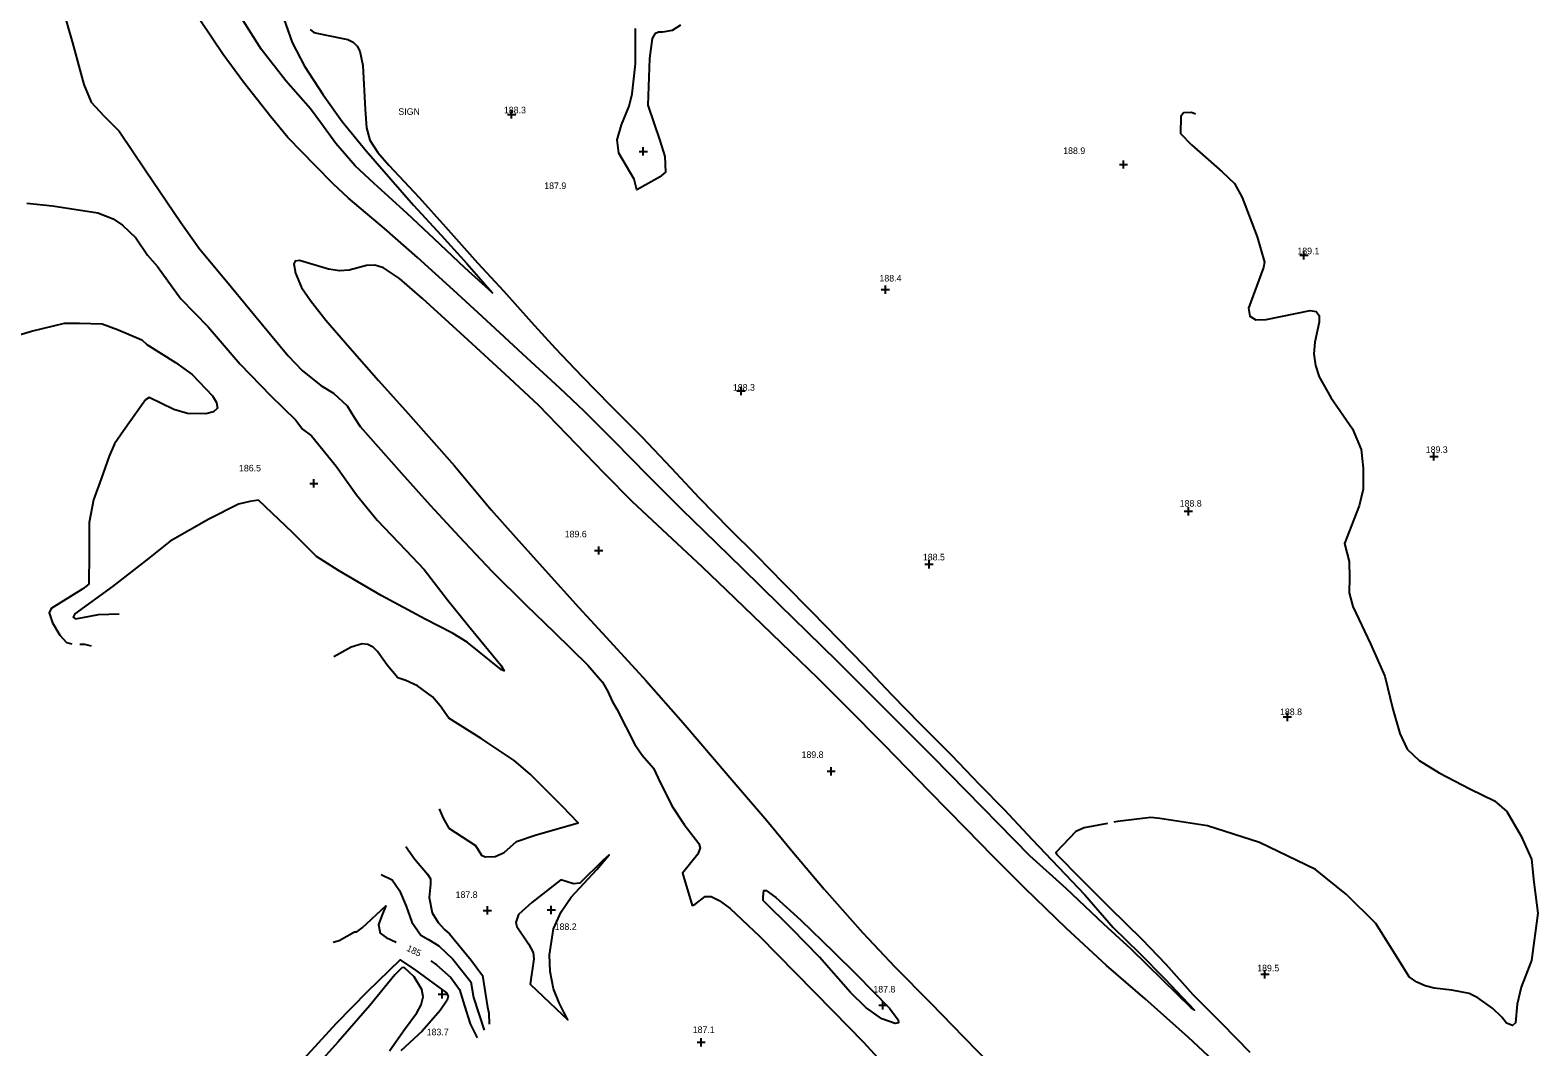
# Model space of a CAD drawing. Extents: x 1467615 to 2003689, y 770235 to 1108726.
# Drawn here: x 1992388.4 to 1992847, y 779287.2 to 779596.3 of the extents above; entities that cross this region are included whole.
import ezdxf

# ---------------------------------------------------------------- set-up
doc = ezdxf.new("R2010")
doc.units = 0
for name, color, linetype in [('RD_DTM_Major1', 7, 'Continuous'), ('RD_DTM_Major1_Lbl', 7, 'Continuous'), ('RD_DTM_Minor1', 7, 'Continuous'), ('RD_DTM_Spot_Elev', 7, 'Continuous'), ('RD_TX_Misc1', 7, 'Continuous')]:
    doc.layers.add(name, color=color, linetype=linetype)

msp = doc.modelspace()

# ---------------------------------------------------------------- linework, layer by layer
at = {"layer": 'RD_DTM_Major1'}
for points in [[(1992480.58, 779319.07), (1992482.42, 779319.56), (1992487.05, 779322.18), (1992487.72, 779322.15), (1992489.4, 779323.42), (1992496.59, 779330.15), (1992495.51, 779327.35), (1992494.38, 779324.42), (1992494.84, 779321.83), (1992496.64, 779320.52), (1992499.68, 779319.07)], [(1992510.25, 779313.36), (1992512.04, 779312.16), (1992516.33, 779308.33), (1992519.04, 779304.69), (1992520.5, 779299.72), (1992522.26, 779294.27), (1992524.38, 779289.97)]]:
    msp.add_lwpolyline(points, dxfattribs=at)
at = {"layer": 'RD_DTM_Minor1'}
for points in [[(1992397.98, 779603.75), (1992401.25, 779592.5), (1992404.72, 779579.82), (1992406.98, 779574.5), (1992410.81, 779570.32), (1992415.5, 779565.64), (1992423.59, 779553.57), (1992434.18, 779537.86), (1992439.93, 779529.87), (1992448.13, 779520), (1992456.66, 779509.71), (1992466.91, 779497.35), (1992471.17, 779492.87), (1992476.81, 779488.33), (1992480.7, 779486.02), (1992484.78, 779482.09), (1992487.02, 779478.47), (1992488.77, 779475.85), (1992494.27, 779469.65), (1992501.33, 779461.64), (1992510.06, 779451.97), (1992518.91, 779442.4), (1992528.86, 779431.83), (1992539.12, 779421.62), (1992547.74, 779413.31), (1992558.03, 779403.23), (1992562.51, 779398.07), (1992564.06, 779395.27), (1992565.43, 779392.38), (1992566.86, 779389.91), (1992572.37, 779379.15), (1992574.55, 779375.91), (1992577.97, 779371.95), (1992579.44, 779368.88), (1992583.55, 779360.49), (1992587.35, 779354.79), (1992591.82, 779349.03), (1992592.18, 779347.75), (1992591.46, 779345.84), (1992586.83, 779340.08), (1992589.79, 779330.2), (1992590.55, 779330.55), (1992593.75, 779332.99), (1992595.5, 779332.91), (1992597.99, 779331.77), (1992601.33, 779329.26), (1992610.23, 779320.84), (1992621.22, 779309.71), (1992632.57, 779298.2), (1992641.91, 779288.67), (1992649.62, 779280.19)], [(1992464.22, 779603.56), (1992468.11, 779592.6), (1992471.87, 779585.45), (1992477.47, 779576.7), (1992483.28, 779568.57), (1992490.58, 779559.69), (1992498.09, 779551.05), (1992505.04, 779543.12), (1992513.41, 779534.03), (1992521.22, 779525.44), (1992529.02, 779516.44), (1992520.62, 779524.12), (1992511.32, 779532.87), (1992503.09, 779540.6), (1992493.08, 779549.71), (1992487.3, 779555.11), (1992481.33, 779561.92), (1992476.78, 779568.13), (1992473.65, 779572.42), (1992466.21, 779580.9), (1992458.65, 779590.6), (1992452.61, 779600.22)], [(1992473.56, 779596.5), (1992474.72, 779595.64), (1992477.99, 779594.89), (1992484.98, 779593.51), (1992486.67, 779592.67), (1992487.89, 779591.51), (1992488.72, 779589.98), (1992489.57, 779585.59), (1992490.31, 779572.27), (1992490.68, 779566.61), (1992491.76, 779562.9), (1992494.14, 779559.17), (1992497.53, 779555.34), (1992506.7, 779545.51), (1992514.77, 779536.57), (1992524.46, 779525.65), (1992532.48, 779516.95), (1992540.8, 779507.71), (1992548.1, 779499.62), (1992556.16, 779491.1), (1992565.07, 779482.11), (1992574.46, 779472.72), (1992583.38, 779463.25), (1992591.91, 779454.17), (1992601.12, 779444.7), (1992609.22, 779436.71), (1992617.59, 779428.19), (1992625.96, 779419.69), (1992634.4, 779411.13), (1992642.06, 779403.18), (1992650.36, 779394.35), (1992659.17, 779385.34), (1992668.62, 779375.91), (1992677.16, 779367.01), (1992684.66, 779359.35), (1992693.19, 779350.27), (1992701.2, 779341.82), (1992709.19, 779333.47), (1992717.87, 779323.49), (1992725.69, 779315.77), (1992733.53, 779307.88), (1992742.6, 779298.34), (1992741.56, 779299.11), (1992732.98, 779307.5), (1992723.25, 779316.9), (1992714.97, 779324.54), (1992703.51, 779335.38), (1992692.46, 779345.32), (1992683.03, 779354.91), (1992673.15, 779365.03), (1992662.88, 779375.53), (1992656.21, 779382.23), (1992645.02, 779393.37), (1992633.94, 779404.37), (1992624.74, 779413.41), (1992616.44, 779421.55), (1992605.12, 779432.64), (1992593.37, 779444.06), (1992586.74, 779450.55), (1992576.41, 779460.88), (1992566.11, 779471.27), (1992556.96, 779480.46), (1992549.53, 779487.47), (1992539.6, 779496.66), (1992527.19, 779508.06), (1992517.17, 779517.29), (1992506.25, 779527.27), (1992496.18, 779536), (1992485.23, 779545.22), (1992480.58, 779549.62), (1992475.23, 779555.12), (1992466.78, 779563.68), (1992461.65, 779570), (1992453.27, 779580.58), (1992447.06, 779588.96), (1992440.24, 779599.19)], [(1992586.26, 779597.87), (1992583.64, 779596.24), (1992580.78, 779595.77), (1992579.5, 779595.71), (1992578.41, 779595.2), (1992577.58, 779593.77), (1992576.75, 779587.76), (1992576.29, 779573.53), (1992579.9, 779562.82), (1992581.42, 779557.94), (1992581.61, 779553.14), (1992579.8, 779551.66), (1992572.9, 779547.83), (1992572.12, 779551), (1992567.42, 779558.91), (1992566.98, 779563), (1992568.25, 779567.57), (1992570.55, 779573.27), (1992571.55, 779576.98), (1992572.53, 779586.12), (1992572.51, 779596.86)], [(1992742.89, 779570.8), (1992741.66, 779571.36), (1992739.17, 779571.17), (1992738.36, 779570.12), (1992738.31, 779564.88), (1992741.63, 779561.53), (1992750.94, 779553.32), (1992754.77, 779549.7), (1992757.02, 779545.51), (1992761.6, 779533.54), (1992763.83, 779525.84), (1992763.52, 779524.16), (1992759.01, 779511.84), (1992759.35, 779509.37), (1992761.26, 779508.31), (1992764.36, 779508.39), (1992777.75, 779511.1), (1992779.58, 779510.76), (1992780.5, 779509.63), (1992780.46, 779507.57), (1992779.16, 779501.5), (1992778.86, 779497.97), (1992779.32, 779494.43), (1992780.47, 779490.97), (1992784, 779484.67), (1992790.58, 779475.18), (1992793.27, 779468.82), (1992793.9, 779463.13), (1992793.9, 779456.81), (1992792.64, 779451.75), (1992788.23, 779440.25), (1992789.57, 779434.81), (1992789.71, 779429.79), (1992789.66, 779425.3), (1992790.75, 779421.08), (1992796.14, 779409.76), (1992800.44, 779399.96), (1992802.88, 779389.9), (1992805, 779382.51), (1992807.28, 779377.74), (1992810.95, 779374.34), (1992816.97, 779370.54), (1992826.47, 779365.59), (1992833.86, 779362.03), (1992837.52, 779358.82), (1992841.95, 779351.24), (1992845.11, 779344.28), (1992845.74, 779337.33), (1992847, 779327.85), (1992845.07, 779313.46), (1992841.91, 779305.37), (1992840.75, 779300.17), (1992840.22, 779294.53), (1992839.32, 779293.74), (1992837.49, 779294.47), (1992836.01, 779296.27), (1992833.31, 779298.87), (1992828.75, 779302.18), (1992826.14, 779303.43), (1992820.85, 779304.48), (1992815.47, 779305.04), (1992812.77, 779305.73), (1992810.2, 779306.87), (1992807.9, 779308.52), (1992804.69, 779313.57), (1992797.69, 779324.69), (1992788.84, 779333.54), (1992779.36, 779341.12), (1992762.29, 779349.34), (1992746.49, 779354.4), (1992732.04, 779356.68), (1992729.24, 779356.91), (1992719.17, 779355.71), (1992718.03, 779355.5)], [(1992387.36, 779543.77), (1992395.21, 779542.91), (1992408.97, 779540.79), (1992413.62, 779538.94), (1992416.48, 779537.01), (1992420.53, 779533.18), (1992424.09, 779527.91), (1992427.17, 779524.46), (1992434.2, 779514.69), (1992442.56, 779506.15), (1992452.32, 779494.83), (1992461.54, 779485.24), (1992469.16, 779477.72), (1992471.19, 779475.04), (1992473.96, 779472.99), (1992481.46, 779463.77), (1992487.71, 779455.03), (1992493.9, 779447.4), (1992502.66, 779438.25), (1992508.27, 779432.35), (1992515.38, 779423.15), (1992521.74, 779415.27), (1992531.54, 779403.23), (1992532.61, 779401.51), (1992531.72, 779401.81), (1992521.32, 779410.25), (1992516.89, 779413.02), (1992508.54, 779417.22), (1992495.17, 779424.45), (1992482.15, 779432.01), (1992475.45, 779436.34), (1992468.15, 779443.65), (1992457.8, 779453.41), (1992455.21, 779453.06), (1992451.72, 779452.24), (1992442.76, 779447.71), (1992431, 779441), (1992424.37, 779435.71), (1992413.4, 779427.15), (1992401.99, 779418.93), (1992401.46, 779417.92), (1992402.16, 779417.37), (1992404.4, 779417.75), (1992409.21, 779418.7), (1992415.51, 779418.91)], [(1992754.29, 779277.37), (1992740.71, 779290.09), (1992727.58, 779301.83), (1992715.81, 779312), (1992703.49, 779323.28), (1992691.06, 779335.4), (1992681.24, 779345.23), (1992673.08, 779353.54), (1992661.99, 779364.88), (1992648.16, 779379.01), (1992636.48, 779390.86), (1992628.01, 779399.29), (1992619.77, 779407.27), (1992611.07, 779415.62), (1992600.19, 779426.1), (1992592.9, 779433.05), (1992583.66, 779441.68), (1992571.63, 779452.96), (1992562.96, 779461.69), (1992554.59, 779470.41), (1992542.98, 779482.3), (1992532.86, 779491.79), (1992521.62, 779502.06), (1992507.75, 779514.75), (1992500.77, 779520.86), (1992495.83, 779524.05), (1992493.21, 779524.85), (1992490.68, 779524.76), (1992485.47, 779523.41), (1992482.48, 779523.15), (1992479.13, 779523.67), (1992470.32, 779526.31), (1992469.01, 779526.15), (1992468.56, 779525.33), (1992469.09, 779522.45), (1992470.95, 779518.13), (1992473.62, 779514.19), (1992478.38, 779508.18), (1992485.6, 779499.75), (1992494.34, 779489.86), (1992503.34, 779479.78), (1992517.42, 779463.84), (1992528.67, 779450.54), (1992536.08, 779442.14), (1992545.08, 779432.18), (1992555.32, 779420.85), (1992564.7, 779410.56), (1992575.82, 779398.51), (1992586.99, 779385.75), (1992600.75, 779369.68), (1992612.46, 779356.01), (1992620.04, 779346.78), (1992629.91, 779335.2), (1992641.68, 779321.86), (1992651.41, 779311.54), (1992662.31, 779300.59), (1992672.42, 779290.21), (1992680.69, 779281.63)], [(1992378.89, 779501.92), (1992388.82, 779504.87), (1992398.83, 779507.24), (1992403.43, 779507.24), (1992410.26, 779507.04), (1992414.99, 779505.35), (1992422.37, 779502.16), (1992423.93, 779500.77), (1992432.62, 779495.28), (1992437.68, 779491.7), (1992443.82, 779485.21), (1992445.12, 779483.15), (1992445.35, 779481.43), (1992444.14, 779480.29), (1992441.86, 779479.69), (1992436.27, 779479.79), (1992432.07, 779481.01), (1992424.58, 779484.63), (1992423.51, 779483.95), (1992416.75, 779474.54), (1992414.02, 779470.58), (1992412.43, 779466.87), (1992409.95, 779459.9), (1992407.63, 779453.59), (1992406.31, 779446.65), (1992406.3, 779437.18), (1992406.19, 779427.89), (1992404.41, 779426.53), (1992394.75, 779420.52), (1992394.22, 779419.14), (1992395.15, 779416.18), (1992397.41, 779412.42), (1992399.47, 779410.12), (1992401.04, 779409.73)], [(1992403.52, 779409.68), (1992404.9, 779409.66), (1992406.94, 779409.19)], [(1992512.83, 779359.61), (1992513.98, 779356.79), (1992515.75, 779353.76), (1992523.88, 779348.42), (1992525.73, 779345.47), (1992526.8, 779344.97), (1992529.83, 779345.14), (1992532.56, 779346.33), (1992536.29, 779349.69), (1992542.04, 779351.57), (1992555.07, 779355.3), (1992550.28, 779360.26), (1992540.44, 779370.11), (1992535.65, 779374.27), (1992525.59, 779381), (1992515.79, 779387.18), (1992513.07, 779390.88), (1992510.73, 779393.61), (1992506.2, 779397.03), (1992502.67, 779398.59), (1992500.25, 779399.47), (1992497.03, 779403.26), (1992494.09, 779407.46), (1992492.72, 779408.75), (1992491.14, 779409.59), (1992489.4, 779409.75), (1992486.02, 779408.76), (1992480.74, 779405.83)], [(1992716.09, 779355.15), (1992708.96, 779353.84), (1992706.48, 779352.72), (1992700.41, 779346.28), (1992700.59, 779345.8), (1992708.24, 779338.13), (1992716.72, 779329.63), (1992726.56, 779319.97), (1992733.89, 779312.38), (1992742.1, 779303.18), (1992750.79, 779294.41), (1992759.35, 779285.66)], [(1992502.71, 779348.15), (1992505.31, 779344.44), (1992509.24, 779339.74), (1992510.17, 779338.34), (1992510.2, 779336.7), (1992509.72, 779332.64), (1992510.69, 779327.96), (1992512.47, 779325.04), (1992514.41, 779322.95), (1992515.9, 779321.58), (1992522.58, 779313.62), (1992525.97, 779308.89), (1992527.51, 779299.33), (1992527.88, 779297.44), (1992528.03, 779294.12)], [(1992549.31, 779300.62), (1992547.55, 779304.88), (1992546.54, 779310.12), (1992546.4, 779315.25), (1992547.59, 779323.06), (1992549.92, 779328.26), (1992552.98, 779332.72), (1992560.79, 779341.1), (1992564.55, 779345.64), (1992562.59, 779343.9), (1992555.58, 779337.04), (1992553.64, 779336.78), (1992549.85, 779338.03), (1992540.98, 779331.12), (1992536.89, 779327.49), (1992536.08, 779325.02), (1992536.4, 779323.86), (1992540, 779318.55), (1992541.41, 779315.93), (1992541.6, 779313.96), (1992540.49, 779306.31), (1992548.43, 779298.82), (1992551.94, 779295.4), (1992550.82, 779297.55), (1992549.31, 779300.62)], [(1992495.19, 779339.62), (1992498.55, 779338.05), (1992500.76, 779334.72), (1992502.8, 779329.98), (1992504.48, 779325.1), (1992507.18, 779321.19), (1992509.57, 779319.84), (1992512.67, 779317.93), (1992516.96, 779313.89), (1992522.43, 779307.03), (1992523.27, 779302.22), (1992526.46, 779292.34)], [(1992611.38, 779332.85), (1992611.58, 779334.77), (1992612.24, 779334.73), (1992615.22, 779332.66), (1992622.83, 779325.77), (1992632.69, 779316.21), (1992639.73, 779309.25), (1992649.77, 779299.01), (1992652.44, 779295.43), (1992652.49, 779294.51), (1992651.5, 779294.29), (1992647.42, 779295.75), (1992642.57, 779299.14), (1992637.97, 779303.8), (1992628.5, 779314.48), (1992620.12, 779323.07), (1992611.32, 779331.72), (1992611.38, 779332.85)], [(1992470.61, 779282.45), (1992481.62, 779294.4), (1992490.98, 779304.09), (1992500.94, 779313.72), (1992505.61, 779310.5), (1992515.02, 779303.68), (1992515.59, 779302.65), (1992515.27, 779301.4), (1992513.13, 779298.27), (1992507.67, 779292), (1992501.14, 779285.98)], [(1992497.71, 779285.99), (1992502.3, 779292.54), (1992506, 779297.53), (1992507.33, 779300), (1992507.93, 779302.41), (1992507.57, 779304.69), (1992505.18, 779308.56), (1992502.15, 779311.37), (1992501.42, 779311.25), (1992499.31, 779309.17), (1992491.75, 779299.8), (1992482.08, 779288.73), (1992471.96, 779277.5)]]:
    msp.add_lwpolyline(points, dxfattribs=at)
at = {"layer": 'RD_DTM_Spot_Elev'}
for p, q in [((1992534.83, 779569.5), (1992534.83, 779572)), ((1992533.58, 779570.75), (1992536.08, 779570.75)), ((1992573.63, 779559.49), (1992576.13, 779559.49)), ((1992574.88, 779558.24), (1992574.88, 779560.74)), ((1992719.73, 779555.5), (1992722.23, 779555.5)), ((1992720.98, 779554.25), (1992720.98, 779556.75)), ((1992774.6, 779527.89), (1992777.1, 779527.89)), ((1992775.85, 779526.64), (1992775.85, 779529.14)), ((1992647.29, 779517.45), (1992649.79, 779517.45)), ((1992648.54, 779516.2), (1992648.54, 779518.7)), ((1992603.39, 779486.65), (1992605.89, 779486.65)), ((1992604.64, 779485.4), (1992604.64, 779487.9)), ((1992814.15, 779466.77), (1992816.65, 779466.77)), ((1992815.4, 779465.52), (1992815.4, 779468.02)), ((1992473.43, 779458.54), (1992475.93, 779458.54)), ((1992474.68, 779457.29), (1992474.68, 779459.79)), ((1992739.46, 779450.05), (1992741.96, 779450.05)), ((1992740.71, 779448.8), (1992740.71, 779451.3)), ((1992561.34, 779436.9), (1992561.34, 779439.4)), ((1992560.09, 779438.15), (1992562.59, 779438.15)), ((1992660.58, 779433.96), (1992663.08, 779433.96)), ((1992661.83, 779432.71), (1992661.83, 779435.21)), ((1992770.81, 779386.27), (1992770.81, 779388.77)), ((1992769.56, 779387.52), (1992772.06, 779387.52)), ((1992630.8, 779371), (1992633.3, 779371)), ((1992632.05, 779369.75), (1992632.05, 779372.25)), ((1992526.21, 779328.72), (1992528.71, 779328.72)), ((1992527.46, 779327.47), (1992527.46, 779329.97)), ((1992545.66, 779328.85), (1992548.16, 779328.85)), ((1992546.91, 779327.6), (1992546.91, 779330.1)), ((1992763.99, 779308.04), (1992763.99, 779310.54)), ((1992762.74, 779309.29), (1992765.24, 779309.29)), ((1992512.51, 779303.2), (1992515.01, 779303.2)), ((1992513.76, 779301.95), (1992513.76, 779304.45)), ((1992647.79, 779298.61), (1992647.79, 779301.11)), ((1992646.54, 779299.86), (1992649.04, 779299.86)), ((1992591.24, 779288.6), (1992593.74, 779288.6)), ((1992592.49, 779287.35), (1992592.49, 779289.85))]:
    msp.add_line(p, q, dxfattribs=at)

# ---------------------------------------------------------------- texts
at = {"layer": 'RD_DTM_Major1_Lbl'}
msp.add_text('185', height=2, rotation=334.496, dxfattribs=at).set_placement((1992502.71, 779316.51))
at = {"layer": 'RD_DTM_Spot_Elev'}
for s, p in [('187.8', (1992517.8, 779332.5)), ('188.2', (1992547.93, 779322.76)), ('187.8', (1992644.88, 779303.75)), ('183.7', (1992509.01, 779290.73)), ('187.1', (1992589.93, 779291.43))]:
    msp.add_text(s, height=2, dxfattribs=at).set_placement(p)
at = {"layer": 'RD_TX_Misc1'}
for s, p in [('SIGN', (1992500.4, 779570.6)), ('188.3', (1992532.5, 779571.06)), ('188.9', (1992702.62, 779558.69)), ('187.9', (1992544.77, 779548.04)), ('189.1', (1992773.86, 779528.21)), ('188.4', (1992646.74, 779519.93)), ('188.3', (1992602.15, 779486.72)), ('189.3', (1992812.89, 779467.81)), ('186.5', (1992451.91, 779462.18)), ('188.8', (1992738.06, 779451.47)), ('189.6', (1992550.99, 779442.12)), ('188.5', (1992659.94, 779435.13)), ('188.8', (1992768.58, 779388.09)), ('189.8', (1992623.03, 779375.07)), ('189.5', (1992761.64, 779310.17))]:
    msp.add_text(s, height=2, dxfattribs=at).set_placement(p)

doc.saveas('drawing.dxf')
